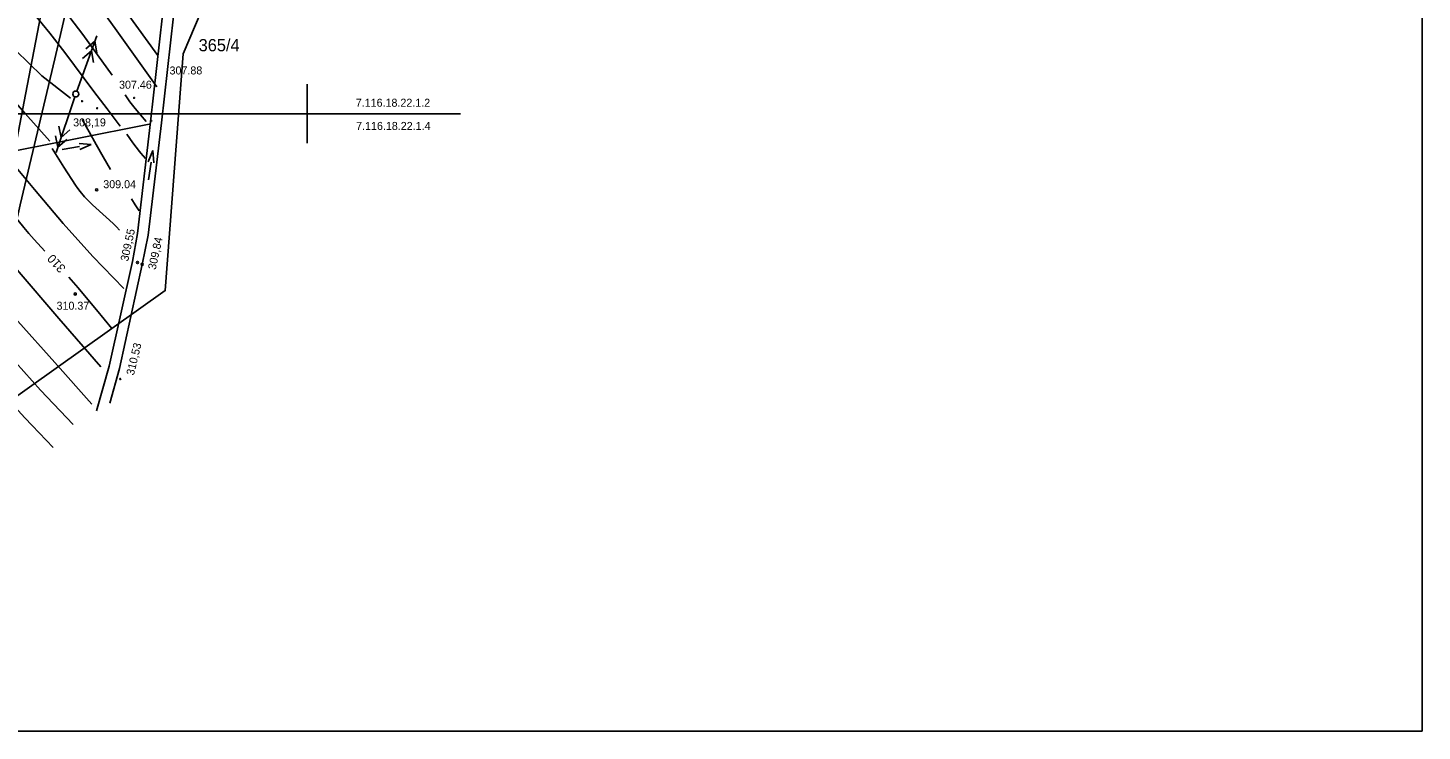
# Model space of a CAD drawing. Extents: x 7477803 to 7478145, y 5500698 to 5500984.
# Drawn here: x 7478026.3 to 7478144.7, y 5500697.6 to 5500757.3 of the extents above; entities that cross this region are included whole.
import ezdxf

# ---------------------------------------------------------------- set-up
doc = ezdxf.new("R2010")
doc.units = 0
for name, color, linetype in [('e_slupy', 7, 'Continuous'), ('eNN', 7, 'Continuous'), ('nazwa_cieku', 7, 'Continuous'), ('nr_dzialki', 7, 'Continuous'), ('pkt_wys', 7, 'Continuous'), ('robocza11', 7, 'Continuous'), ('robocza49', 7, 'Continuous'), ('robocza50', 7, 'Continuous'), ('rowy', 7, 'Continuous'), ('w', 7, 'Continuous'), ('warst_ciagla', 7, 'Continuous'), ('warst_opis', 7, 'Continuous'), ('warst_pogrub', 7, 'Continuous'), ('warst_przeryw', 7, 'Continuous'), ('zakresy', 7, 'Continuous')]:
    doc.layers.add(name, color=color, linetype=linetype)

# ---------------------------------------------------------------- blocks, each defined once
blk = doc.blocks.new('511_5')
at = {"layer": 'e_slupy'}
blk.add_circle((0, 0), 0.25, dxfattribs=at)
blk = doc.blocks.new('993')
at = {"layer": 'nazwa_cieku'}
for p, q in [((0, 0), (1.5, 0)), ((1.5, 0.25), (2.5, 0)), ((2.5, 0), (1.5, -0.25))]:
    blk.add_line(p, q, dxfattribs=at)
blk = doc.blocks.new('993_5')
at = {"layer": 'nazwa_cieku'}
for p, q in [((1.5, 0), (0, 0)), ((2.5, 0), (1.5, 0.25)), ((2.5, 0), (1.5, -0.25))]:
    blk.add_line(p, q, dxfattribs=at)
blk = doc.blocks.new('140')
at = {"layer": 'pkt_wys'}
blk.add_circle((0, 0), 0.045, dxfattribs=at)
blk.add_circle((0, 0), 0.045, dxfattribs=at)
blk = doc.blocks.new('801_2')
at = {"layer": 'pkt_wys'}
blk.add_circle((0, 0), 0.09, dxfattribs=at)
blk.add_circle((0, 0), 0.09, dxfattribs=at)
blk = doc.blocks.new('SUPE03')
at = {"layer": 'e_slupy'}
for p, q in [((5, 0), (105, 0)), ((78, 0), (60.7, 10)), ((60.7, -10), (78, 0)), ((95.3, 0), (78, 10)), ((78, -10), (95.3, 0))]:
    blk.add_line(p, q, dxfattribs=at)
blk = doc.blocks.new('SUPE3')
at = {"layer": 'e_slupy', "xscale": 0.05, "yscale": 0.05000000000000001}
blk.add_blockref('SUPE03', (0, 0), dxfattribs=at)

msp = doc.modelspace()

# ---------------------------------------------------------------- linework, layer by layer
at = {"layer": 'eNN'}
msp.add_lwpolyline([(7478021.08, 5500721.8), (7478022.35, 5500727.71), (7478025.64, 5500742.27), (7478028.58, 5500754.67), (7478031.01, 5500765.16)], dxfattribs=at)
at = {"layer": 'robocza11'}
msp.add_lwpolyline([(7478015, 5500697.57), (7478144.73, 5500697.57), (7478144.73, 5500983.57), (7477803.26, 5500983.57), (7477803.26, 5500697.57), (7478010.82, 5500697.57)], close=True, dxfattribs=at)
at = {"layer": 'robocza49'}
for p, q in [((7478050, 5500750), (7478050, 5500752.5)), ((7478000, 5500750), (7478063.04, 5500750)), ((7478050, 5500747.5), (7478050, 5500750))]:
    msp.add_line(p, q, dxfattribs=at)
at = {"layer": 'rowy'}
for p, q in [((7478036.69, 5500749.37), (7478036.85, 5500749.4)), ((7478016.42, 5500745.09), (7478036.73, 5500749.13))]:
    msp.add_line(p, q, dxfattribs=at)
for points in [[(7478032.12, 5500724.76), (7478033.2, 5500728.55), (7478035.16, 5500737.45), (7478035.6, 5500739.82), (7478036.71, 5500749.3), (7478038.22, 5500762.92)], [(7478039.16, 5500762.83), (7478037.64, 5500749.22), (7478036.51, 5500739.69), (7478036, 5500737.2), (7478034.07, 5500728.35)], [(7478034.07, 5500728.35), (7478033.25, 5500725.42)]]:
    msp.add_lwpolyline(points, dxfattribs=at)
at = {"layer": 'w'}
msp.add_lwpolyline([(7478028.93, 5500766.53), (7478026.09, 5500751.63), (7478024.78, 5500744.81), (7478022.83, 5500734.61), (7478021.57, 5500727.76), (7478020.31, 5500723.11), (7478018.73, 5500717.36)], dxfattribs=at)
at = {"layer": 'warst_ciagla'}
for points in [[(7478037.23, 5500752.29), (7478035.53, 5500754.66), (7478033.84, 5500757.03), (7478030.6, 5500761.55), (7478027.36, 5500766.07), (7478026.56, 5500767.25), (7478026.35, 5500767.54), (7478026.19, 5500767.74), (7478026.06, 5500767.9), (7478025.86, 5500768.12), (7478025.64, 5500768.32), (7478024.85, 5500769.03), (7478024.05, 5500769.74)], [(7478034.13, 5500748.93), (7478033.01, 5500750.41), (7478031.89, 5500751.88), (7478029.43, 5500755.19), (7478028.16, 5500756.83), (7478027.51, 5500757.63), (7478026.84, 5500758.41), (7478025.12, 5500760.36), (7478023.4, 5500762.31)], [(7478028.14, 5500747.67), (7478026.06, 5500750.02), (7478023.98, 5500752.36), (7478023.39, 5500753.01), (7478022.93, 5500753.5), (7478022.6, 5500753.86), (7478022.35, 5500754.14), (7478021.99, 5500754.57), (7478021.82, 5500754.79), (7478021.66, 5500755.02), (7478021.13, 5500755.76), (7478020.61, 5500756.51)], [(7478034.68, 5500748.26), (7478035.21, 5500747.53), (7478035.48, 5500747.16), (7478035.76, 5500746.8), (7478035.89, 5500746.65), (7478036.08, 5500746.42), (7478036.27, 5500746.19)], [(7478028.34, 5500747.03), (7478029.34, 5500745.47), (7478030.34, 5500743.92), (7478030.53, 5500743.64), (7478030.72, 5500743.39), (7478031.1, 5500742.95), (7478031.45, 5500742.58), (7478031.77, 5500742.27), (7478032.94, 5500741.2), (7478033.52, 5500740.67), (7478033.8, 5500740.39), (7478034.06, 5500740.1)], [(7478031.73, 5500725.34), (7478028.57, 5500728.86), (7478025.42, 5500732.38), (7478024.79, 5500733.11), (7478023.71, 5500734.4), (7478022.11, 5500736.35), (7478021.28, 5500737.31), (7478020.43, 5500738.24), (7478018.7, 5500740.05), (7478016.97, 5500741.86)], [(7478028.44, 5500721.65), (7478027.84, 5500722.28), (7478027.24, 5500722.9), (7478026.64, 5500723.53), (7478026.04, 5500724.16), (7478025.45, 5500724.8), (7478024.86, 5500725.43), (7478024.56, 5500725.75), (7478024.27, 5500726.08), (7478024.13, 5500726.24), (7478023.98, 5500726.4), (7478023.91, 5500726.48), (7478023.84, 5500726.56), (7478023.77, 5500726.64), (7478023.7, 5500726.72), (7478023.3, 5500727.19), (7478022.9, 5500727.66), (7478022.51, 5500728.13), (7478022.12, 5500728.61), (7478021.74, 5500729.08), (7478021.35, 5500729.56), (7478020.96, 5500730.04), (7478020.58, 5500730.51)]]:
    msp.add_lwpolyline(points, dxfattribs=at)
at = {"layer": 'warst_pogrub'}
for points in [[(7478027.72, 5500738.33), (7478026.82, 5500739.32), (7478026.38, 5500739.82), (7478025.95, 5500740.33), (7478023.75, 5500742.99), (7478021.54, 5500745.64)], [(7478033.42, 5500731.77), (7478032.11, 5500733.34), (7478030.8, 5500734.91), (7478030.55, 5500735.22), (7478030.16, 5500735.66), (7478029.77, 5500736.11)]]:
    msp.add_lwpolyline(points, dxfattribs=at)
at = {"layer": 'warst_przeryw'}
for points in [[(7478024.74, 5500775.28), (7478028.18, 5500770.44), (7478030.56, 5500764.88), (7478033.8, 5500759.81), (7478037.33, 5500754.93)], [(7478023.48, 5500767.12), (7478025.83, 5500763.56), (7478028.37, 5500760.13), (7478030.95, 5500756.73), (7478033.45, 5500753.27)], [(7478021.79, 5500760.44), (7478023.52, 5500757.9), (7478025.27, 5500755.37), (7478027.46, 5500753.21), (7478029.91, 5500751.32)], [(7478034.55, 5500751.6), (7478034.95, 5500751.01), (7478035.4, 5500750.44), (7478035.86, 5500749.89), (7478036.32, 5500749.33)], [(7478033.29, 5500745.27), (7478032.69, 5500746.33), (7478032.1, 5500747.39), (7478031.5, 5500748.45), (7478030.9, 5500749.51)], [(7478034.44, 5500735.15), (7478031.81, 5500737.86), (7478029.29, 5500740.67), (7478026.84, 5500743.55), (7478024.44, 5500746.46)], [(7478032.47, 5500728.5), (7478028.92, 5500732.62), (7478025.37, 5500736.74), (7478021.54, 5500740.61), (7478017.61, 5500744.37)], [(7478035.73, 5500741.75), (7478035.41, 5500742.26), (7478035.08, 5500742.77)], [(7478015.93, 5500737.52), (7478020.14, 5500734.31), (7478023.79, 5500730.47), (7478027.35, 5500726.53), (7478030.12, 5500723.59)]]:
    msp.add_lwpolyline(points, dxfattribs=at)
at = {"layer": 'zakresy'}
msp.add_lwpolyline([(7477995.06, 5500962.35), (7477983.95, 5500968.08), (7477970.78, 5500968.61), (7477936.09, 5500958.17), (7477930.51, 5500954.34), (7477914.3, 5500958.58), (7477904.32, 5500957.41), (7477897.27, 5500950.87), (7477811.42, 5500829.34), (7477936, 5500769.49), (7478008.98, 5500726.58), (7478019.4, 5500721.78), (7478037.95, 5500734.97), (7478039.49, 5500755.09), (7478043.98, 5500765.71), (7478067.54, 5500795.07), (7478092.11, 5500820.25), (7478076.16, 5500837.99), (7478068.11, 5500851.15), (7478061.42, 5500873.3), (7478054.13, 5500876.37), (7478039.67, 5500897.64), (7478026.36, 5500915.23), (7478015.05, 5500927.73)], close=True, dxfattribs=at)

# ---------------------------------------------------------------- block references
at = {"layer": 'e_slupy'}
for name, rotation in [('SUPE3', 70.09031651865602), ('511_5', 0.0626175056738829), ('SUPE3', -108.5893847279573)]:
    msp.add_blockref(name, (7478030.35, 5500751.67), dxfattribs=dict(at, rotation=rotation))
at = {"layer": 'nazwa_cieku'}
for name, p, rotation in [('993_5', (7478029.19, 5500746.97), 9.524939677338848), ('993', (7478036.52, 5500744.39), 81.37626293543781)]:
    msp.add_blockref(name, p, dxfattribs=dict(at, rotation=rotation))
at = {"layer": 'pkt_wys', "rotation": 0.0626175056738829}
for name, p in [('140', (7478030.89, 5500751.06)), ('140', (7478032.17, 5500750.46)), ('140', (7478035.31, 5500751.34)), ('801_2', (7478032.13, 5500743.54)), ('801_2', (7478035.6, 5500737.36)), ('801_2', (7478036, 5500737.2)), ('801_2', (7478030.31, 5500734.69)), ('140', (7478034.13, 5500727.47))]:
    msp.add_blockref(name, p, dxfattribs=at)

# ---------------------------------------------------------------- texts
at = {"layer": 'nr_dzialki'}
msp.add_text('365/4', height=1.04, dxfattribs=at).set_placement((7478040.79, 5500755.3))
at = {"layer": 'pkt_wys'}
for s, rotation, p in [('307.88', 0.0626, (7478038.32, 5500753.33)), ('307.46', 0.0626, (7478034.03, 5500752.12)), ('308,19', 0.0626, (7478030.13, 5500748.92)), ('309.04', 0.0626, (7478032.69, 5500743.67)), ('309,55', 77.6086, (7478034.8, 5500737.42)), ('309,84', 77.6849, (7478037.14, 5500736.71)), ('310.37', 0.0626, (7478028.72, 5500733.35)), ('310,53', 76.4236, (7478035.29, 5500727.74))]:
    msp.add_text(s, height=0.68, rotation=rotation, dxfattribs=at).set_placement(p)
at = {"layer": 'robocza50'}
for s, p in [('7.116.18.22.1.2', (7478054.14, 5500750.59)), ('7.116.18.22.1.4', (7478054.17, 5500748.62))]:
    msp.add_text(s, height=0.68, dxfattribs=at).set_placement(p)
at = {"layer": 'warst_opis'}
msp.add_text('310', height=0.75, rotation=132.8594, dxfattribs=at).set_placement((7478029.55, 5500736.91))

doc.saveas('drawing.dxf')
